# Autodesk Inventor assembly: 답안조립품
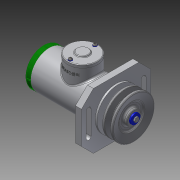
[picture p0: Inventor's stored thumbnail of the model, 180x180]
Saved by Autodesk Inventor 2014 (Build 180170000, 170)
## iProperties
Created: 2017-10
Part Number: 답안조립품
Document SubType Name: Assembly
Designer: geosung1
Author: geosung1
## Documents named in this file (20)
- C:\Users\geosung1\Desktop\471008V1006\답안조립품.iam
- C:\Users\geosung1\Desktop\471008V1006\본체.ipt
- C:\Users\geosung1\Desktop\471008V1006\사이드 커버.ipt
- 사이드 커버.ipt
- C:\Users\geosung1\Desktop\471008V1006\베어링 15 x 35 x 11.ipt
- C:\Users\geosung1\Desktop\471008V1006\멈춤링 35x1.6.ipt
- C:\Users\geosung1\Desktop\471008V1006\부시1.ipt
- C:\Users\geosung1\Desktop\471008V1006\축.ipt
- C:\Users\geosung1\Desktop\471008V1006\부시2.ipt
- C:\Users\geosung1\Desktop\471008V1006\와셔 10x21.ipt
- C:\Users\geosung1\Desktop\471008V1006\너트 M10.ipt
- C:\Users\geosung1\Desktop\471008V1006\멈춤링 15 x 1.ipt
- C:\Users\geosung1\Desktop\471008V1006\오일 실 15 25 7.ipt
- C:\Users\geosung1\Desktop\471008V1006\탑 커버.ipt
- C:\Users\geosung1\Desktop\471008V1006\키 4 x 4 x 18.ipt
- C:\Users\geosung1\Desktop\471008V1006\V-벨트풀리.ipt
- C:\Users\geosung1\Desktop\471008V1006\와셔 4x16.ipt
- C:\Users\geosung1\Desktop\471008V1006\볼트 M4 x 10.ipt
- C:\Users\geosung1\Desktop\471008V1006\와셔 3x6.ipt
- C:\Users\geosung1\Desktop\471008V1006\십자볼트 M3 x 10.ipt
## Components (2 placed, 2 different names)
1. V-벨트풀리:1 — 각도:3
2. ISO 4017 M4 x 10:1 — 각도:4
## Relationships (2: Angle 2)
- 각도:3 [Angle]: V-벨트풀리:1
- 각도:4 [Angle]: ISO 4017 M4 x 10:1
